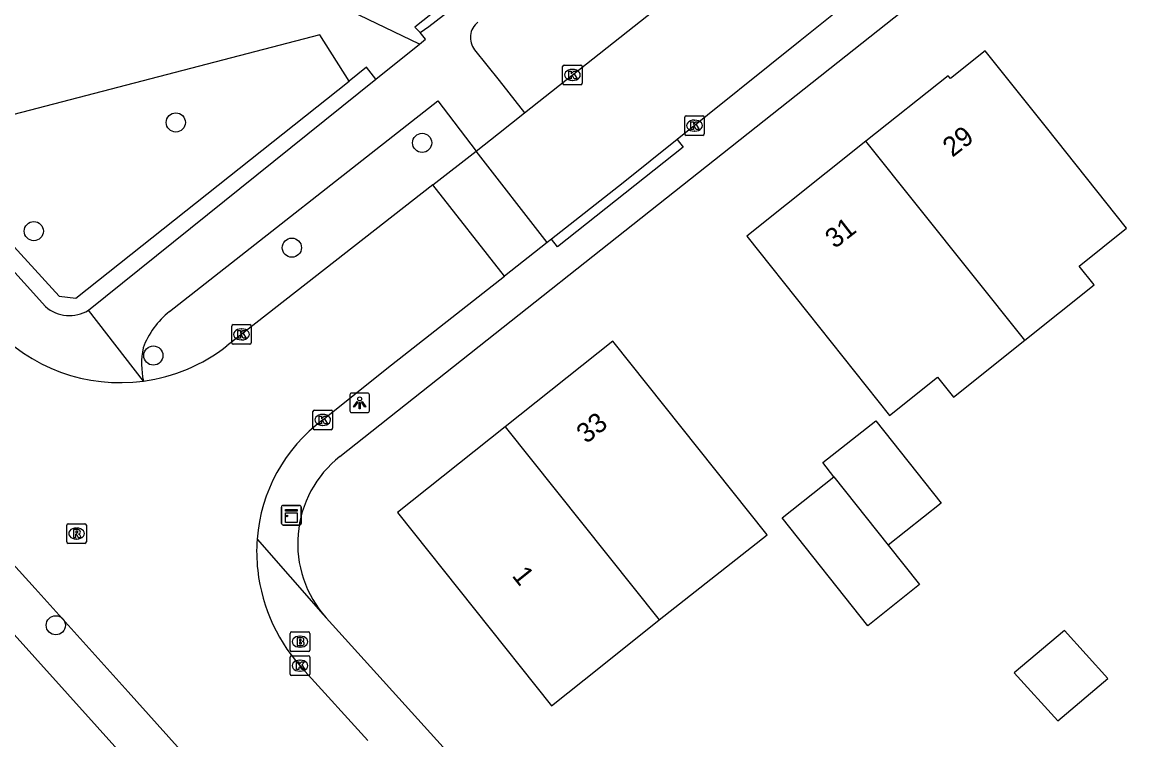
# Model space of a CAD drawing. Extents: x 161772 to 163123, y 383092 to 383917.
# Drawn here: x 162608.5 to 162665.1, y 383557.9 to 383594.6 of the extents above; entities that cross this region are included whole.
import ezdxf

# ---------------------------------------------------------------- set-up
doc = ezdxf.new("R2010")
doc.units = 0
for name, color, linetype in [('IMGEO_Boom', 7, 'Continuous'), ('IMGEO_Brandkraan', 7, 'Continuous'), ('IMGEO_Groenvoorziening', 7, 'Continuous'), ('IMGEO_Haag', 7, 'Continuous'), ('IMGEO_Kast', 7, 'Continuous'), ('IMGEO_Kolk', 7, 'Continuous'), ('IMGEO_Lichtpunt', 7, 'Continuous'), ('IMGEO_Pand', 7, 'Continuous'), ('IMGEO_Pand_nummerreeks', 7, 'Continuous'), ('IMGEO_Rijbaan_lokaal_open', 7, 'Continuous'), ('IMGEO_Rioolput', 7, 'Continuous'), ('IMGEO_Voetpad_open', 7, 'Continuous')]:
    doc.layers.add(name, color=color, linetype=linetype)

msp = doc.modelspace()

# ---------------------------------------------------------------- linework, layer by layer
at = {"layer": 'IMGEO_Boom'}
for centre in [(162616.34, 383589.434), (162628.913, 383588.392), (162609.093, 383583.886), (162622.264, 383583.041), (162615.196, 383577.536), (162610.216, 383563.77)]:
    msp.add_circle(centre, 0.489, dxfattribs=at)
at = {"layer": 'IMGEO_Brandkraan'}
for p, q in [((162622.18, 383562.506), (162622.18, 383563.358)), ((162622.255, 383563.432), (162623.107, 383563.432)), ((162623.181, 383563.358), (162623.181, 383562.506)), ((162622.668, 383563.212), (162622.693, 383563.212)), ((162623.107, 383562.432), (162622.255, 383562.432)), ((162622.691, 383562.652), (162622.666, 383562.652))]:
    msp.add_line(p, q, dxfattribs=at)
for points in [[(162622.18, 383562.506), (162622.18, 383563.358)], [(162622.255, 383563.432), (162623.107, 383563.432)], [(162623.181, 383563.358), (162623.181, 383562.506)], [(162622.528, 383563.132), (162622.528, 383562.732), (162622.741, 383562.732)], [(162622.759, 383563.132), (162622.528, 383563.132)], [(162622.707, 383563.051), (162622.653, 383563.051), (162622.653, 383562.975)], [(162622.653, 383562.975), (162622.706, 383562.975)], [(162622.715, 383562.899), (162622.653, 383562.899), (162622.653, 383562.818)], [(162622.653, 383562.818), (162622.715, 383562.818)], [(162623.107, 383562.432), (162622.255, 383562.432)]]:
    msp.add_lwpolyline(points, dxfattribs=at)
for centre, radius, start, end in [((162622.257, 383563.356), 0.0765, 91.552, 178.448), ((162622.257, 383563.356), 0.0765, 91.552, 178.448), ((162623.105, 383563.356), 0.0765, 1.552, 88.448), ((162623.105, 383563.356), 0.0765, 1.552, 88.448), ((162622.708, 383563.013), 0.0379, 267.8285, 90.9355), ((162622.716, 383562.858), 0.0404, 269.8759, 90.5077), ((162622.747, 383562.983), 0.251, 268.6676, 293.5347), ((162622.763, 383562.987), 0.145, 59.4692, 91.5367), ((162622.788, 383563.034), 0.0922, 285.5137, 58.1501), ((162622.793, 383562.842), 0.105, 301.3115, 78.989), ((162622.257, 383562.508), 0.0765, 181.552, 268.448), ((162622.257, 383562.508), 0.0765, 181.552, 268.448), ((162623.105, 383562.508), 0.0765, 271.552, 358.448), ((162623.105, 383562.508), 0.0765, 271.552, 358.448)]:
    msp.add_arc(centre, radius, start, end, dxfattribs=at)
for centre, major_axis, ratio, start_param, end_param in [((162622.667, 383562.932), (-0.387, 0.002), 0.722429, 4.712389, 7.853982), ((162622.692, 383562.932), (-0.39, 0.002), 0.717154, 1.570796, 4.712389)]:
    msp.add_ellipse(centre, major_axis=major_axis, ratio=ratio, start_param=start_param, end_param=end_param, dxfattribs=at)
at = {"layer": 'IMGEO_Groenvoorziening'}
for points in [[(162628.785, 383593.437), (162622.234, 383596.598), (162612.52, 383598.872), (162608.784, 383604.086), (162593.429, 383599.123)], [(162625.191, 383591.547), (162623.696, 383593.908), (162603.09, 383588.551)]]:
    msp.add_lwpolyline(points, dxfattribs=at)
at = {"layer": 'IMGEO_Haag'}
for points in [[(162630.748, 383596.071), (162628.543, 383594.304), (162628.816, 383594.02)], [(162626.551, 383591.64), (162626.081, 383592.254), (162625.191, 383591.547)], [(162603.09, 383588.551), (162610.383, 383580.57), (162611.241, 383580.46), (162625.191, 383591.547)]]:
    msp.add_lwpolyline(points, dxfattribs=at)
at = {"layer": 'IMGEO_Kast'}
for p, q in [((162621.739, 383568.961), (162621.739, 383569.802)), ((162621.739, 383569.802), (162621.739, 383568.961)), ((162621.814, 383569.886), (162622.655, 383569.886)), ((162622.655, 383569.886), (162621.814, 383569.886)), ((162622.739, 383569.811), (162622.739, 383568.97)), ((162622.739, 383568.97), (162622.739, 383569.811)), ((162622.664, 383568.886), (162621.823, 383568.886)), ((162621.823, 383568.886), (162622.664, 383568.886))]:
    msp.add_line(p, q, dxfattribs=at)
for points in [[(162621.934, 383569.676), (162622.534, 383569.676), (162622.534, 383569.591), (162621.934, 383569.591), (162621.934, 383569.676)], [(162621.934, 383569.501), (162622.534, 383569.501), (162622.534, 383569.012), (162621.934, 383569.012), (162621.934, 383569.501)]]:
    msp.add_lwpolyline(points, dxfattribs=at)
msp.add_circle((162622.018, 383569.35), 0.0377, dxfattribs=at)
for centre, start, end in [((162621.817, 383569.808), 92.4484, 184.2845), ((162621.817, 383569.808), 92.4484, 184.2845), ((162622.661, 383569.808), 2.4484, 94.2845), ((162622.661, 383569.808), 2.4484, 94.2845), ((162621.817, 383568.964), 182.4484, 274.2845), ((162621.817, 383568.964), 182.4484, 274.2845), ((162622.661, 383568.964), 272.4484, 4.2845), ((162622.661, 383568.964), 272.4484, 4.2845)]:
    msp.add_arc(centre, 0.0779, start, end, dxfattribs=at)
at = {"layer": 'IMGEO_Kolk'}
for p, q in [((162636.084, 383591.432), (162636.084, 383592.284)), ((162636.159, 383592.358), (162637.011, 383592.358)), ((162637.085, 383592.284), (162637.085, 383591.432)), ((162636.572, 383592.138), (162636.597, 383592.138)), ((162637.011, 383591.358), (162636.159, 383591.358)), ((162636.595, 383591.578), (162636.57, 383591.578)), ((162642.315, 383588.845), (162642.315, 383589.697)), ((162642.39, 383589.771), (162643.242, 383589.771)), ((162642.803, 383589.551), (162642.828, 383589.551)), ((162643.316, 383589.697), (162643.316, 383588.845)), ((162642.826, 383588.991), (162642.801, 383588.991)), ((162643.242, 383588.771), (162642.39, 383588.771)), ((162619.194, 383578.191), (162619.194, 383579.043)), ((162619.269, 383579.117), (162620.121, 383579.117)), ((162619.682, 383578.897), (162619.707, 383578.897)), ((162620.195, 383579.043), (162620.195, 383578.191)), ((162620.121, 383578.117), (162619.269, 383578.117)), ((162619.705, 383578.337), (162619.68, 383578.337)), ((162623.34, 383573.824), (162623.34, 383574.676)), ((162623.415, 383574.75), (162624.267, 383574.75)), ((162624.341, 383574.676), (162624.341, 383573.824)), ((162623.828, 383574.53), (162623.853, 383574.53)), ((162624.267, 383573.75), (162623.415, 383573.75)), ((162623.851, 383573.97), (162623.826, 383573.97)), ((162622.253, 383562.209), (162623.105, 383562.209)), ((162622.178, 383561.283), (162622.178, 383562.135)), ((162622.666, 383561.989), (162622.691, 383561.989)), ((162623.179, 383562.135), (162623.179, 383561.283)), ((162623.105, 383561.209), (162622.253, 383561.209)), ((162622.689, 383561.429), (162622.664, 383561.429))]:
    msp.add_line(p, q, dxfattribs=at)
for points in [[(162636.084, 383591.432), (162636.084, 383592.284)], [(162636.159, 383592.358), (162637.011, 383592.358)], [(162637.085, 383592.284), (162637.085, 383591.432)], [(162636.405, 383592.058), (162636.528, 383592.058), (162636.528, 383591.907), (162636.658, 383592.058), (162636.822, 383592.058), (162636.676, 383591.907), (162636.829, 383591.658), (162636.677, 383591.658), (162636.592, 383591.822), (162636.528, 383591.755), (162636.528, 383591.658), (162636.405, 383591.658), (162636.405, 383592.058)], [(162637.011, 383591.358), (162636.159, 383591.358)], [(162642.315, 383588.845), (162642.315, 383589.697)], [(162642.39, 383589.771), (162643.242, 383589.771)], [(162642.636, 383589.471), (162642.759, 383589.471), (162642.759, 383589.32), (162642.889, 383589.471), (162643.053, 383589.471), (162642.907, 383589.32), (162643.06, 383589.071), (162642.908, 383589.071), (162642.823, 383589.235), (162642.759, 383589.168), (162642.759, 383589.071), (162642.636, 383589.071), (162642.636, 383589.471)], [(162643.316, 383589.697), (162643.316, 383588.845)], [(162643.242, 383588.771), (162642.39, 383588.771)], [(162619.194, 383578.191), (162619.194, 383579.043)], [(162619.269, 383579.117), (162620.121, 383579.117)], [(162619.515, 383578.817), (162619.638, 383578.817), (162619.638, 383578.666), (162619.768, 383578.817), (162619.932, 383578.817), (162619.786, 383578.666), (162619.939, 383578.417), (162619.787, 383578.417), (162619.702, 383578.581), (162619.638, 383578.514), (162619.638, 383578.417), (162619.515, 383578.417), (162619.515, 383578.817)], [(162620.195, 383579.043), (162620.195, 383578.191)], [(162620.121, 383578.117), (162619.269, 383578.117)], [(162623.34, 383573.824), (162623.34, 383574.676)], [(162623.415, 383574.75), (162624.267, 383574.75)], [(162624.341, 383574.676), (162624.341, 383573.824)], [(162623.661, 383574.45), (162623.784, 383574.45), (162623.784, 383574.299), (162623.914, 383574.45), (162624.078, 383574.45), (162623.932, 383574.299), (162624.085, 383574.05), (162623.933, 383574.05), (162623.848, 383574.214), (162623.784, 383574.147), (162623.784, 383574.05), (162623.661, 383574.05), (162623.661, 383574.45)], [(162624.267, 383573.75), (162623.415, 383573.75)], [(162622.253, 383562.209), (162623.105, 383562.209)], [(162622.178, 383561.283), (162622.178, 383562.135)], [(162622.499, 383561.909), (162622.622, 383561.909), (162622.622, 383561.758), (162622.752, 383561.909), (162622.916, 383561.909), (162622.77, 383561.758), (162622.923, 383561.509), (162622.771, 383561.509), (162622.686, 383561.673), (162622.622, 383561.606), (162622.622, 383561.509), (162622.499, 383561.509), (162622.499, 383561.909)], [(162623.179, 383562.135), (162623.179, 383561.283)], [(162623.105, 383561.209), (162622.253, 383561.209)]]:
    msp.add_lwpolyline(points, dxfattribs=at)
for centre, start, end in [((162636.161, 383592.282), 91.552, 178.448), ((162636.161, 383592.282), 91.552, 178.448), ((162637.009, 383592.282), 1.552, 88.448), ((162637.009, 383592.282), 1.552, 88.448), ((162636.161, 383591.434), 181.552, 268.448), ((162636.161, 383591.434), 181.552, 268.448), ((162637.009, 383591.434), 271.552, 358.448), ((162637.009, 383591.434), 271.552, 358.448), ((162642.392, 383589.695), 91.552, 178.448), ((162642.392, 383589.695), 91.552, 178.448), ((162643.24, 383589.695), 1.552, 88.448), ((162643.24, 383589.695), 1.552, 88.448), ((162642.392, 383588.847), 181.552, 268.448), ((162642.392, 383588.847), 181.552, 268.448), ((162643.24, 383588.847), 271.552, 358.448), ((162643.24, 383588.847), 271.552, 358.448), ((162619.271, 383579.041), 91.552, 178.448), ((162619.271, 383579.041), 91.552, 178.448), ((162620.119, 383579.041), 1.552, 88.448), ((162620.119, 383579.041), 1.552, 88.448), ((162619.271, 383578.193), 181.552, 268.448), ((162619.271, 383578.193), 181.552, 268.448), ((162620.119, 383578.193), 271.552, 358.448), ((162620.119, 383578.193), 271.552, 358.448), ((162623.417, 383574.674), 91.552, 178.448), ((162623.417, 383574.674), 91.552, 178.448), ((162624.265, 383574.674), 1.552, 88.448), ((162624.265, 383574.674), 1.552, 88.448), ((162623.417, 383573.826), 181.552, 268.448), ((162623.417, 383573.826), 181.552, 268.448), ((162624.265, 383573.826), 271.552, 358.448), ((162624.265, 383573.826), 271.552, 358.448), ((162622.255, 383562.133), 91.552, 178.448), ((162622.255, 383562.133), 91.552, 178.448), ((162623.103, 383562.133), 1.552, 88.448), ((162623.103, 383562.133), 1.552, 88.448), ((162622.255, 383561.285), 181.552, 268.448), ((162622.255, 383561.285), 181.552, 268.448), ((162623.103, 383561.285), 271.552, 358.448), ((162623.103, 383561.285), 271.552, 358.448)]:
    msp.add_arc(centre, 0.0765, start, end, dxfattribs=at)
for centre, major_axis, ratio, start_param, end_param in [((162636.571, 383591.858), (-0.387, 0.002), 0.722429, 4.712389, 7.853982), ((162636.596, 383591.858), (-0.39, 0.002), 0.717154, 1.570796, 4.712389), ((162642.802, 383589.271), (-0.387, 0.002), 0.722429, 4.712389, 7.853982), ((162642.827, 383589.271), (-0.39, 0.002), 0.717154, 1.570796, 4.712389), ((162619.681, 383578.617), (-0.387, 0.002), 0.722429, 4.712389, 7.853982), ((162619.706, 383578.617), (-0.39, 0.002), 0.717154, 1.570796, 4.712389), ((162623.827, 383574.25), (-0.387, 0.002), 0.722429, 4.712389, 7.853982), ((162623.852, 383574.25), (-0.39, 0.002), 0.717154, 1.570796, 4.712389), ((162622.665, 383561.709), (-0.387, 0.002), 0.722429, 4.712389, 7.853982), ((162622.69, 383561.709), (-0.39, 0.002), 0.717154, 1.570796, 4.712389)]:
    msp.add_ellipse(centre, major_axis=major_axis, ratio=ratio, start_param=start_param, end_param=end_param, dxfattribs=at)
at = {"layer": 'IMGEO_Lichtpunt'}
for p, q in [((162625.226, 383575.525), (162625.226, 383574.718)), ((162625.226, 383575.525), (162625.226, 383574.718)), ((162626.128, 383575.62), (162625.32, 383575.62)), ((162626.128, 383575.62), (162625.32, 383575.62)), ((162626.222, 383574.718), (162626.222, 383575.525)), ((162626.222, 383574.718), (162626.222, 383575.525)), ((162625.32, 383574.624), (162626.128, 383574.624)), ((162625.32, 383574.624), (162626.128, 383574.624))]:
    msp.add_line(p, q, dxfattribs=at)
for points in [[(162625.6, 383575.189), (162625.639, 383575.161), (162625.451, 383574.899), (162625.413, 383574.926), (162625.6, 383575.189)], [(162625.702, 383575.141), (162625.749, 383575.141), (162625.749, 383574.819), (162625.702, 383574.819), (162625.702, 383575.141)], [(162625.812, 383575.161), (162625.85, 383575.188), (162626.037, 383574.926), (162625.998, 383574.898), (162625.812, 383575.161)]]:
    msp.add_lwpolyline(points, dxfattribs=at)
msp.add_circle((162625.725, 383575.323), 0.0994, dxfattribs=at)
for centre, start, end in [((162625.32, 383575.525), 90, 180), ((162625.32, 383575.525), 90, 180), ((162626.128, 383575.525), 0, 90), ((162626.128, 383575.525), 0, 90), ((162625.32, 383574.718), 180, 270), ((162625.32, 383574.718), 180, 270), ((162626.128, 383574.718), 270, 0), ((162626.128, 383574.718), 270, 360)]:
    msp.add_arc(centre, 0.0946, start, end, dxfattribs=at)
at = {"layer": 'IMGEO_Pand'}
for points in [[(162659.675, 383578.317), (162663.21, 383581.138), (162662.444, 383582.098), (162664.874, 383584.035), (162660.777, 383589.181), (162657.66, 383593.09), (162655.881, 383591.671), (162655.762, 383591.82), (162651.569, 383588.475)], [(162651.569, 383588.475), (162645.483, 383583.621), (162648.601, 383579.712), (162652.77, 383574.475), (162655.223, 383576.434), (162656.037, 383575.414), (162659.675, 383578.317)], [(162659.675, 383578.317), (162651.569, 383588.475)], [(162641.01, 383564.047), (162646.532, 383568.381), (162638.64, 383578.275), (162633.152, 383573.898)], [(162649.932, 383571.354), (162649.367, 383572.072), (162652.066, 383574.212), (162655.4, 383570.003), (162652.702, 383567.863)], [(162633.152, 383573.898), (162627.663, 383569.52), (162635.524, 383559.665), (162638.013, 383561.653), (162641.01, 383564.047)], [(162633.152, 383573.898), (162641.01, 383564.047)], [(162652.702, 383567.863), (162654.304, 383565.844), (162651.663, 383563.747), (162647.29, 383569.257), (162649.932, 383571.354)], [(162649.932, 383571.354), (162652.702, 383567.863)], [(162659.135, 383561.336), (162661.355, 383558.887), (162663.913, 383561.061), (162661.693, 383563.509), (162659.135, 383561.336)]]:
    msp.add_lwpolyline(points, dxfattribs=at)
at = {"layer": 'IMGEO_Rijbaan_lokaal_open'}
for points in [[(162653.738, 383598.039), (162648.206, 383593.595), (162641.932, 383588.565)], [(162634.137, 383589.916), (162642.17, 383596.28)], [(162631.666, 383587.972), (162632.807, 383588.863), (162634.137, 383589.916)], [(162641.932, 383588.565), (162639.177, 383586.356), (162635.512, 383583.478)], [(162629.459, 383586.247), (162631.666, 383587.972)], [(162635.3, 383583.311), (162631.666, 383587.972)], [(162629.459, 383586.247), (162618.941, 383578.025)], [(162633.113, 383581.594), (162629.459, 383586.247)], [(162635.3, 383583.311), (162633.113, 383581.594)], [(162635.512, 383583.478), (162635.3, 383583.311)], [(162623.843, 383574.254), (162627.114, 383576.883), (162633.113, 383581.594)], [(162605.068, 383570.161), (162609.157, 383565.647), (162613.905, 383560.374), (162616.436, 383557.563), (162620.646, 383552.888)], [(162626.143, 383557.885), (162622.931, 383561.434)]]:
    msp.add_lwpolyline(points, dxfattribs=at)
for centre, radius, start, end in [((162613.505, 383584.981), 8.829, 221.9435, 277.7061), ((162613.501, 383584.988), 8.837, 277.7287, 308.0001), ((162628.827, 383567.543), 8.359, 126.6, 175.7264), ((162628.803, 383567.538), 8.336, 175.6791, 186.6268), ((162629.238, 383567.522), 8.766, 186.1979, 223.9895)]:
    msp.add_arc(centre, radius, start, end, dxfattribs=at)
at = {"layer": 'IMGEO_Rioolput'}
for p, q in [((162610.775, 383568.026), (162610.775, 383568.878)), ((162610.85, 383568.952), (162611.702, 383568.952)), ((162611.263, 383568.732), (162611.288, 383568.732)), ((162611.776, 383568.878), (162611.776, 383568.026)), ((162611.702, 383567.952), (162610.85, 383567.952)), ((162611.286, 383568.172), (162611.261, 383568.172))]:
    msp.add_line(p, q, dxfattribs=at)
for points in [[(162610.775, 383568.026), (162610.775, 383568.878)], [(162610.85, 383568.952), (162611.702, 383568.952)], [(162611.364, 383568.65), (162611.112, 383568.652), (162611.112, 383568.252)], [(162611.112, 383568.252), (162611.236, 383568.252), (162611.236, 383568.414), (162611.247, 383568.414)], [(162611.29, 383568.571), (162611.236, 383568.571), (162611.236, 383568.49)], [(162611.236, 383568.49), (162611.288, 383568.49)], [(162611.776, 383568.878), (162611.776, 383568.026)], [(162611.702, 383567.952), (162610.85, 383567.952)], [(162611.294, 383568.385), (162611.365, 383568.252), (162611.505, 383568.252), (162611.44, 383568.378)]]:
    msp.add_lwpolyline(points, dxfattribs=at)
for centre, radius, start, end in [((162610.852, 383568.876), 0.0765, 91.552, 178.448), ((162610.852, 383568.876), 0.0765, 91.552, 178.448), ((162611.246, 383568.361), 0.0533, 26.0293, 88.6989), ((162611.272, 383568.679), 0.19, 274.7715, 282.9687), ((162611.296, 383568.475), 0.0964, 77.0061, 93.1865), ((162611.31, 383568.532), 0.0378, 276.6634, 79.6772), ((162611.363, 383568.54), 0.109, 350.3612, 89.416), ((162611.361, 383568.54), 0.112, 277.5842, 350.9817), ((162611.345, 383568.325), 0.108, 29.5134, 73.7905), ((162611.7, 383568.876), 0.0765, 1.552, 88.448), ((162611.7, 383568.876), 0.0765, 1.552, 88.448), ((162610.852, 383568.028), 0.0765, 181.552, 268.448), ((162610.852, 383568.028), 0.0765, 181.552, 268.448), ((162611.7, 383568.028), 0.0765, 271.552, 358.448), ((162611.7, 383568.028), 0.0765, 271.552, 358.448)]:
    msp.add_arc(centre, radius, start, end, dxfattribs=at)
for centre, major_axis, ratio, start_param, end_param in [((162611.262, 383568.452), (-0.387, 0.002), 0.722429, 4.712389, 7.853982), ((162611.287, 383568.452), (-0.39, 0.002), 0.717154, 1.570796, 4.712389)]:
    msp.add_ellipse(centre, major_axis=major_axis, ratio=ratio, start_param=start_param, end_param=end_param, dxfattribs=at)
at = {"layer": 'IMGEO_Voetpad_open'}
for points in [[(162624.721, 383572.388), (162687.563, 383622.167), (162778.983, 383695.388), (162783.083, 383695.752)], [(162641.081, 383522.035), (162642.837, 383523.629), (162638.19, 383528.735), (162638.592, 383529.182), (162625.201, 383544.257), (162586.698, 383587.072), (162561.346, 383615.02), (162560.835, 383615.634)], [(162628.816, 383594.02), (162629.261, 383594.323), (162631.281, 383595.918), (162647.625, 383608.825)], [(162609.688, 383580.04), (162602.21, 383588.322), (162592.67, 383598.878), (162590.018, 383601.813), (162586.45, 383605.761)], [(162628.785, 383593.437), (162629.086, 383593.679), (162628.816, 383594.02)], [(162626.551, 383591.64), (162628.785, 383593.437)], [(162631.595, 383593.14), (162632.852, 383591.572), (162634.137, 383589.916)], [(162611.889, 383579.849), (162626.551, 383591.64)], [(162616.016, 383579.783), (162629.709, 383590.532), (162631.666, 383587.972)], [(162641.932, 383588.565), (162642.242, 383588.173), (162635.822, 383583.086), (162635.512, 383583.478)], [(162614.689, 383576.232), (162611.889, 383579.849)], [(162620.491, 383568.166), (162623.863, 383564.318), (162624.015, 383564.152)], [(162641.032, 383545.232), (162636.927, 383549.874), (162624.015, 383564.152)]]:
    msp.add_lwpolyline(points, dxfattribs=at)
for centre, radius, start, end in [((162632.371, 383593.765), 0.996, 127.9517, 218.869), ((162610.918, 383581.433), 1.858, 228.5576, 301.5232), ((162618.784, 383576.364), 4.399, 128.9939, 159.1866), ((162618.789, 383577.121), 4.195, 168.9197, 192.2296), ((162628.222, 383567.94), 5.661, 128.2074, 221.9936)]:
    msp.add_arc(centre, radius, start, end, dxfattribs=at)

# ---------------------------------------------------------------- texts
at = {"layer": 'IMGEO_Pand_nummerreeks'}
for s, rotation, p in [('29', 37.8691, (162655.977, 383587.625)), ('31', 37.8691, (162649.977, 383582.961)), ('33', 38.5744, (162637.295, 383573.006)), ('1', 308.5782, (162633.463, 383566.29))]:
    msp.add_text(s, height=1, rotation=rotation, dxfattribs=at).set_placement(p)

doc.saveas('drawing.dxf')
